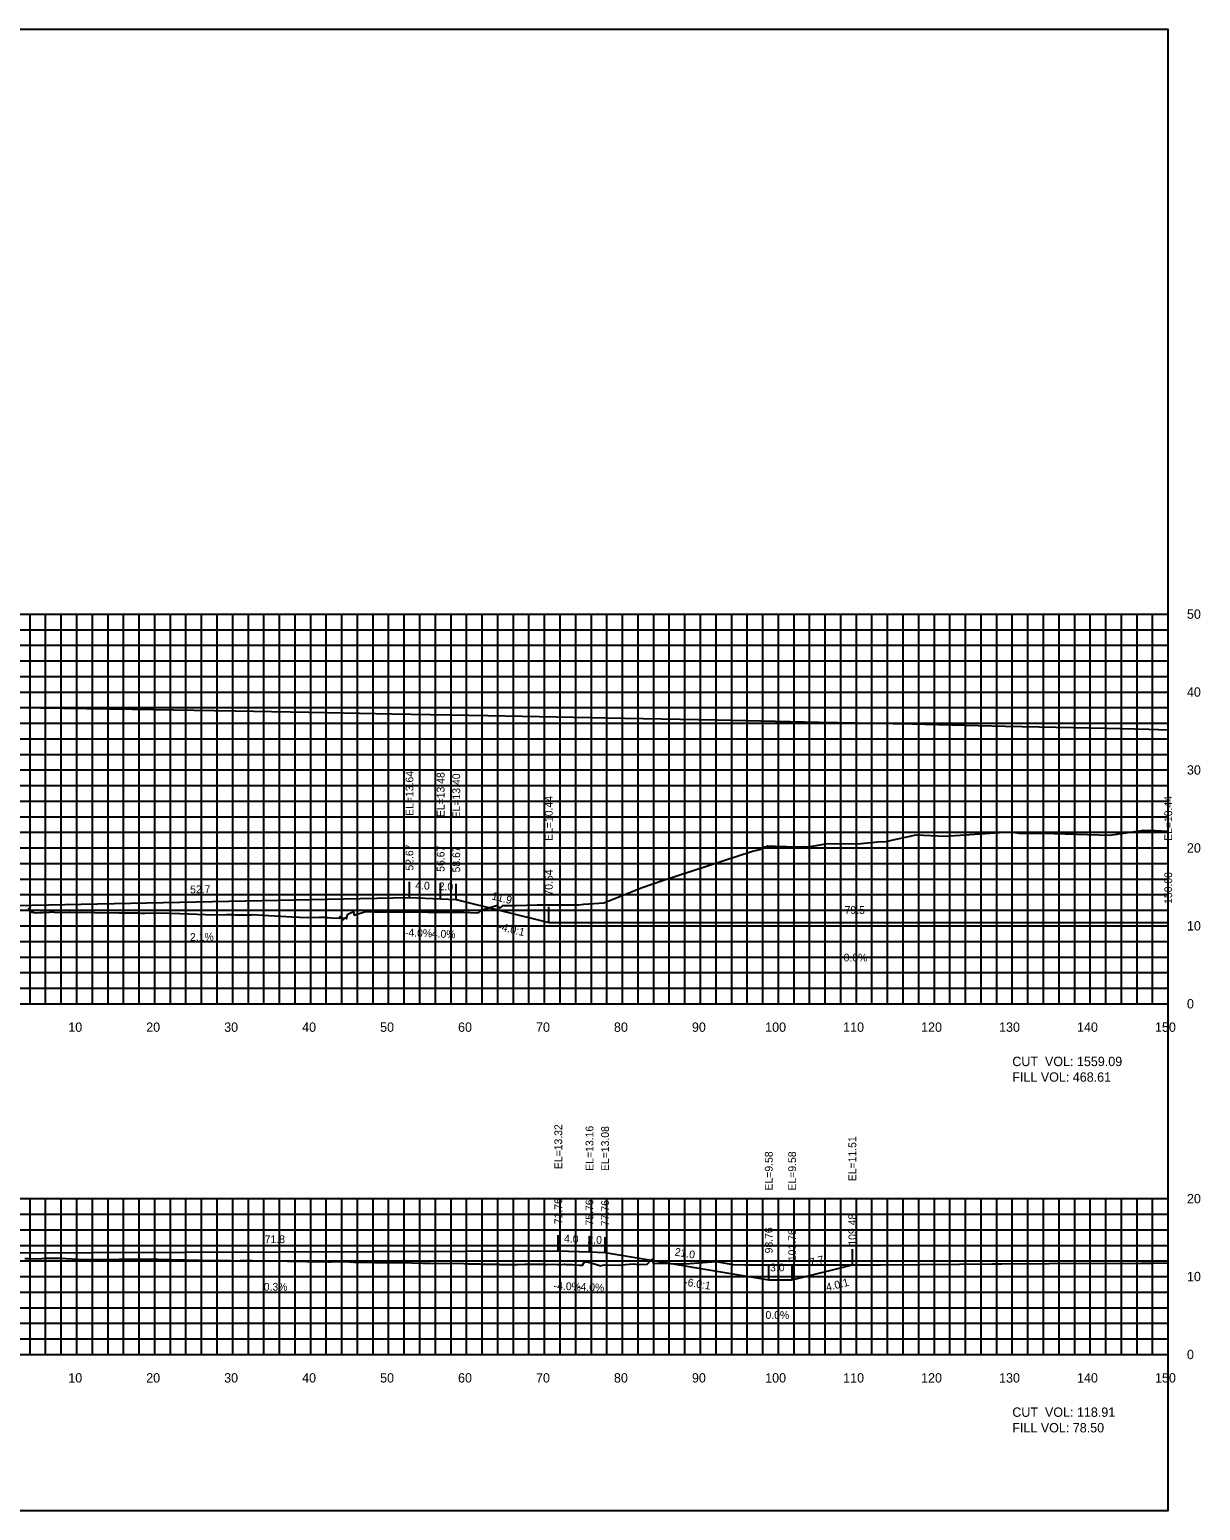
# Model space of a CAD drawing. Extents: x 1797419 to 1809236, y 248759 to 251512.
# Drawn here: x 1802974.9 to 1803125.1, y 250417.3 to 250607.3 of the extents above; entities that cross this region are included whole.
import ezdxf

# ---------------------------------------------------------------- set-up
doc = ezdxf.new("R2010")
doc.units = 0
for name, color, linetype in [('10', 7, 'Continuous'), ('3', 7, 'Continuous'), ('31', 7, 'Continuous'), ('4', 7, 'Continuous'), ('60', 7, 'Continuous'), ('ANNO-TXT', 7, 'Continuous'), ('CL-CNST', 7, 'Continuous'), ('Level 62', 7, 'Continuous'), ('M-ROADS', 7, 'Continuous')]:
    doc.layers.add(name, color=color, linetype=linetype)

msp = doc.modelspace()

# ---------------------------------------------------------------- linework, layer by layer
for p, q in [((1803023.67, 250495.9), (1803023.67, 250497.9)), ((1803027.67, 250495.74), (1803027.67, 250497.74)), ((1803029.67, 250495.66), (1803029.67, 250497.66)), ((1803041.54, 250492.69), (1803041.54, 250494.69)), ((1803121, 250492.69), (1803121, 250494.69)), ((1803042.76, 250450.57), (1803042.76, 250452.57)), ((1803046.76, 250450.41), (1803046.76, 250452.41)), ((1803048.76, 250450.33), (1803048.76, 250452.33)), ((1803080.48, 250448.76), (1803080.48, 250450.76)), ((1803069.76, 250446.83), (1803069.76, 250448.83)), ((1803072.76, 250446.83), (1803072.76, 250448.83))]:
    msp.add_line(p, q)
msp.add_lwpolyline([(1802821, 250417.26), (1803121, 250417.26), (1803121, 250607.26), (1802821, 250607.26)], close=True)
at = {"layer": '60'}
for p, q in [((1803121, 250482.26), (1803121, 250532.26)), ((1803121.06, 250532.26), (1803121, 250532.26)), ((1803121.06, 250522.26), (1803121, 250522.26)), ((1803121.06, 250512.26), (1803121, 250512.26)), ((1803121.06, 250502.26), (1803121, 250502.26)), ((1803121.06, 250492.26), (1803121, 250492.26)), ((1802821, 250482.26), (1803121, 250482.26)), ((1802981, 250482.2), (1802981, 250482.26)), ((1802991, 250482.2), (1802991, 250482.26)), ((1803001, 250482.2), (1803001, 250482.26)), ((1803011, 250482.2), (1803011, 250482.26)), ((1803021, 250482.2), (1803021, 250482.26)), ((1803031, 250482.2), (1803031, 250482.26)), ((1803041, 250482.2), (1803041, 250482.26)), ((1803051, 250482.2), (1803051, 250482.26)), ((1803061, 250482.2), (1803061, 250482.26)), ((1803071, 250482.2), (1803071, 250482.26)), ((1803081, 250482.2), (1803081, 250482.26)), ((1803091, 250482.2), (1803091, 250482.26)), ((1803101, 250482.2), (1803101, 250482.26)), ((1803111, 250482.2), (1803111, 250482.26)), ((1803121, 250482.2), (1803121, 250482.26)), ((1803121.06, 250482.26), (1803121, 250482.26)), ((1803121, 250437.26), (1803121, 250457.26)), ((1803121.06, 250457.26), (1803121, 250457.26)), ((1803121.06, 250447.26), (1803121, 250447.26)), ((1802821, 250437.26), (1803121, 250437.26)), ((1802981, 250437.2), (1802981, 250437.26)), ((1802991, 250437.2), (1802991, 250437.26)), ((1803001, 250437.2), (1803001, 250437.26)), ((1803011, 250437.2), (1803011, 250437.26)), ((1803021, 250437.2), (1803021, 250437.26)), ((1803031, 250437.2), (1803031, 250437.26)), ((1803041, 250437.2), (1803041, 250437.26)), ((1803051, 250437.2), (1803051, 250437.26)), ((1803061, 250437.2), (1803061, 250437.26)), ((1803071, 250437.2), (1803071, 250437.26)), ((1803081, 250437.2), (1803081, 250437.26)), ((1803091, 250437.2), (1803091, 250437.26)), ((1803101, 250437.2), (1803101, 250437.26)), ((1803111, 250437.2), (1803111, 250437.26)), ((1803121, 250437.2), (1803121, 250437.26)), ((1803121.06, 250437.26), (1803121, 250437.26))]:
    msp.add_line(p, q, dxfattribs=at)
at = {"layer": 'CL-CNST'}
for points in [[(1802963.13, 250520.45), (1802976.35, 250520.24), (1802988.13, 250520.05), (1803001.31, 250519.83), (1803013.13, 250519.62), (1803021.41, 250519.47), (1803028.86, 250519.34), (1803028.86, 250519.34), (1803028.86, 250519.34), (1803033.73, 250519.25), (1803038.13, 250519.17), (1803051.25, 250518.91), (1803063.13, 250518.68), (1803076.21, 250518.41), (1803088.13, 250518.16), (1803100.07, 250517.9), (1803113.13, 250517.61), (1803118.53, 250517.49), (1803121, 250517.43)], [(1802904, 250493.23), (1802906, 250493.31), (1802910, 250493.47), (1802971, 250494.81), (1803023.67, 250495.9), (1803027.67, 250495.74), (1803029.67, 250495.66), (1803041.54, 250492.69), (1803121, 250492.69)], [(1802862.48, 250449.62), (1802880, 250445.24), (1802883, 250445.24), (1802904, 250448.74), (1802906, 250448.82), (1802910, 250448.98), (1802971, 250450.32), (1803042.76, 250450.57), (1803046.76, 250450.41), (1803048.76, 250450.33), (1803069.76, 250446.83), (1803072.76, 250446.83), (1803080.48, 250448.76)]]:
    msp.add_lwpolyline(points, dxfattribs=at)
at = {"layer": 'Level 62'}
for p, q in [((1802821, 250532.26), (1803121, 250532.26)), ((1802975, 250482.26), (1802975, 250532.26)), ((1802977, 250482.26), (1802977, 250532.26)), ((1802979, 250482.26), (1802979, 250532.26)), ((1802981, 250482.26), (1802981, 250532.26)), ((1802983, 250482.26), (1802983, 250532.26)), ((1802985, 250482.26), (1802985, 250532.26)), ((1802987, 250482.26), (1802987, 250532.26)), ((1802989, 250482.26), (1802989, 250532.26)), ((1802991, 250482.26), (1802991, 250532.26)), ((1802993, 250482.26), (1802993, 250532.26)), ((1802995, 250482.26), (1802995, 250532.26)), ((1802997, 250482.26), (1802997, 250532.26)), ((1802999, 250482.26), (1802999, 250532.26)), ((1803001, 250482.26), (1803001, 250532.26)), ((1803003, 250482.26), (1803003, 250532.26)), ((1803005, 250482.26), (1803005, 250532.26)), ((1803007, 250482.26), (1803007, 250532.26)), ((1803009, 250482.26), (1803009, 250532.26)), ((1803011, 250482.26), (1803011, 250532.26)), ((1803013, 250482.26), (1803013, 250532.26)), ((1803015, 250482.26), (1803015, 250532.26)), ((1803017, 250482.26), (1803017, 250532.26)), ((1803019, 250482.26), (1803019, 250532.26)), ((1803021, 250482.26), (1803021, 250532.26)), ((1803023, 250482.26), (1803023, 250532.26)), ((1803025, 250482.26), (1803025, 250532.26)), ((1803027, 250482.26), (1803027, 250532.26)), ((1803029, 250482.26), (1803029, 250532.26)), ((1803031, 250482.26), (1803031, 250532.26)), ((1803033, 250482.26), (1803033, 250532.26)), ((1803035, 250482.26), (1803035, 250532.26)), ((1803037, 250482.26), (1803037, 250532.26)), ((1803039, 250482.26), (1803039, 250532.26)), ((1803041, 250482.26), (1803041, 250532.26)), ((1803043, 250482.26), (1803043, 250532.26)), ((1803045, 250482.26), (1803045, 250532.26)), ((1803047, 250482.26), (1803047, 250532.26)), ((1803049, 250482.26), (1803049, 250532.26)), ((1803051, 250482.26), (1803051, 250532.26)), ((1803053, 250482.26), (1803053, 250532.26)), ((1803055, 250482.26), (1803055, 250532.26)), ((1803057, 250482.26), (1803057, 250532.26)), ((1803059, 250482.26), (1803059, 250532.26)), ((1803061, 250482.26), (1803061, 250532.26)), ((1803063, 250482.26), (1803063, 250532.26)), ((1803065, 250482.26), (1803065, 250532.26)), ((1803067, 250482.26), (1803067, 250532.26)), ((1803069, 250482.26), (1803069, 250532.26)), ((1803071, 250482.26), (1803071, 250532.26)), ((1803073, 250482.26), (1803073, 250532.26)), ((1803075, 250482.26), (1803075, 250532.26)), ((1803077, 250482.26), (1803077, 250532.26)), ((1803079, 250482.26), (1803079, 250532.26)), ((1803081, 250482.26), (1803081, 250532.26)), ((1803083, 250482.26), (1803083, 250532.26)), ((1803085, 250482.26), (1803085, 250532.26)), ((1803087, 250482.26), (1803087, 250532.26)), ((1803089, 250482.26), (1803089, 250532.26)), ((1803091, 250482.26), (1803091, 250532.26)), ((1803093, 250482.26), (1803093, 250532.26)), ((1803095, 250482.26), (1803095, 250532.26)), ((1803097, 250482.26), (1803097, 250532.26)), ((1803099, 250482.26), (1803099, 250532.26)), ((1803101, 250482.26), (1803101, 250532.26)), ((1803103, 250482.26), (1803103, 250532.26)), ((1803105, 250482.26), (1803105, 250532.26)), ((1803107, 250482.26), (1803107, 250532.26)), ((1803109, 250482.26), (1803109, 250532.26)), ((1803111, 250482.26), (1803111, 250532.26)), ((1803113, 250482.26), (1803113, 250532.26)), ((1803115, 250482.26), (1803115, 250532.26)), ((1803117, 250482.26), (1803117, 250532.26)), ((1803119, 250482.26), (1803119, 250532.26)), ((1803121, 250482.26), (1803121, 250532.26)), ((1802821, 250530.26), (1803121, 250530.26)), ((1802821, 250528.26), (1803121, 250528.26)), ((1802821, 250526.26), (1803121, 250526.26)), ((1802821, 250524.26), (1803121, 250524.26)), ((1802821, 250522.26), (1803121, 250522.26)), ((1802821, 250520.26), (1803121, 250520.26)), ((1802821, 250518.26), (1803121, 250518.26)), ((1802821, 250516.26), (1803121, 250516.26)), ((1802821, 250514.26), (1803121, 250514.26)), ((1802821, 250512.26), (1803121, 250512.26)), ((1802821, 250510.26), (1803121, 250510.26)), ((1802821, 250508.26), (1803121, 250508.26)), ((1802821, 250506.26), (1803121, 250506.26)), ((1802821, 250504.26), (1803121, 250504.26)), ((1802821, 250502.26), (1803121, 250502.26)), ((1802821, 250500.26), (1803121, 250500.26)), ((1802821, 250498.26), (1803121, 250498.26)), ((1802821, 250496.26), (1803121, 250496.26)), ((1802821, 250494.26), (1803121, 250494.26)), ((1802821, 250492.26), (1803121, 250492.26)), ((1802821, 250490.26), (1803121, 250490.26)), ((1802821, 250488.26), (1803121, 250488.26)), ((1802821, 250486.26), (1803121, 250486.26)), ((1802821, 250484.26), (1803121, 250484.26)), ((1802821, 250482.26), (1803121, 250482.26)), ((1802821, 250457.26), (1803121, 250457.26)), ((1802975, 250437.26), (1802975, 250457.26)), ((1802977, 250437.26), (1802977, 250457.26)), ((1802979, 250437.26), (1802979, 250457.26)), ((1802981, 250437.26), (1802981, 250457.26)), ((1802983, 250437.26), (1802983, 250457.26)), ((1802985, 250437.26), (1802985, 250457.26)), ((1802987, 250437.26), (1802987, 250457.26)), ((1802989, 250437.26), (1802989, 250457.26)), ((1802991, 250437.26), (1802991, 250457.26)), ((1802993, 250437.26), (1802993, 250457.26)), ((1802995, 250437.26), (1802995, 250457.26)), ((1802997, 250437.26), (1802997, 250457.26)), ((1802999, 250437.26), (1802999, 250457.26)), ((1803001, 250437.26), (1803001, 250457.26)), ((1803003, 250437.26), (1803003, 250457.26)), ((1803005, 250437.26), (1803005, 250457.26)), ((1803007, 250437.26), (1803007, 250457.26)), ((1803009, 250437.26), (1803009, 250457.26)), ((1803011, 250437.26), (1803011, 250457.26)), ((1803013, 250437.26), (1803013, 250457.26)), ((1803015, 250437.26), (1803015, 250457.26)), ((1803017, 250437.26), (1803017, 250457.26)), ((1803019, 250437.26), (1803019, 250457.26)), ((1803021, 250437.26), (1803021, 250457.26)), ((1803023, 250437.26), (1803023, 250457.26)), ((1803025, 250437.26), (1803025, 250457.26)), ((1803027, 250437.26), (1803027, 250457.26)), ((1803029, 250437.26), (1803029, 250457.26)), ((1803031, 250437.26), (1803031, 250457.26)), ((1803033, 250437.26), (1803033, 250457.26)), ((1803035, 250437.26), (1803035, 250457.26)), ((1803037, 250437.26), (1803037, 250457.26)), ((1803039, 250437.26), (1803039, 250457.26)), ((1803041, 250437.26), (1803041, 250457.26)), ((1803043, 250437.26), (1803043, 250457.26)), ((1803045, 250437.26), (1803045, 250457.26)), ((1803047, 250437.26), (1803047, 250457.26)), ((1803049, 250437.26), (1803049, 250457.26)), ((1803051, 250437.26), (1803051, 250457.26)), ((1803053, 250437.26), (1803053, 250457.26)), ((1803055, 250437.26), (1803055, 250457.26)), ((1803057, 250437.26), (1803057, 250457.26)), ((1803059, 250437.26), (1803059, 250457.26)), ((1803061, 250437.26), (1803061, 250457.26)), ((1803063, 250437.26), (1803063, 250457.26)), ((1803065, 250437.26), (1803065, 250457.26)), ((1803067, 250437.26), (1803067, 250457.26)), ((1803069, 250437.26), (1803069, 250457.26)), ((1803071, 250437.26), (1803071, 250457.26)), ((1803073, 250437.26), (1803073, 250457.26)), ((1803075, 250437.26), (1803075, 250457.26)), ((1803077, 250437.26), (1803077, 250457.26)), ((1803079, 250437.26), (1803079, 250457.26)), ((1803081, 250437.26), (1803081, 250457.26)), ((1803083, 250437.26), (1803083, 250457.26)), ((1803085, 250437.26), (1803085, 250457.26)), ((1803087, 250437.26), (1803087, 250457.26)), ((1803089, 250437.26), (1803089, 250457.26)), ((1803091, 250437.26), (1803091, 250457.26)), ((1803093, 250437.26), (1803093, 250457.26)), ((1803095, 250437.26), (1803095, 250457.26)), ((1803097, 250437.26), (1803097, 250457.26)), ((1803099, 250437.26), (1803099, 250457.26)), ((1803101, 250437.26), (1803101, 250457.26)), ((1803103, 250437.26), (1803103, 250457.26)), ((1803105, 250437.26), (1803105, 250457.26)), ((1803107, 250437.26), (1803107, 250457.26)), ((1803109, 250437.26), (1803109, 250457.26)), ((1803111, 250437.26), (1803111, 250457.26)), ((1803113, 250437.26), (1803113, 250457.26)), ((1803115, 250437.26), (1803115, 250457.26)), ((1803117, 250437.26), (1803117, 250457.26)), ((1803119, 250437.26), (1803119, 250457.26)), ((1803121, 250437.26), (1803121, 250457.26)), ((1802821, 250455.26), (1803121, 250455.26)), ((1802821, 250453.26), (1803121, 250453.26)), ((1802821, 250451.26), (1803121, 250451.26)), ((1802821, 250449.26), (1803121, 250449.26)), ((1802821, 250447.26), (1803121, 250447.26)), ((1802821, 250445.26), (1803121, 250445.26)), ((1802821, 250443.26), (1803121, 250443.26)), ((1802821, 250441.26), (1803121, 250441.26)), ((1802821, 250439.26), (1803121, 250439.26)), ((1802821, 250437.26), (1803121, 250437.26))]:
    msp.add_line(p, q, dxfattribs=at)
at = {"layer": 'M-ROADS'}
for points in [[(1802974.82, 250494.57), (1802975.06, 250494.21), (1802975.16, 250494.05), (1802975.17, 250494.03), (1802975.18, 250494.03), (1802975.27, 250494.04), (1802975.32, 250494.02), (1802975.35, 250494.02), (1802975.38, 250494.02), (1802975.39, 250494.01), (1802975.4, 250494.01), (1802975.41, 250494.01), (1802975.41, 250494.01), (1802975.42, 250494.01), (1802975.43, 250493.97), (1802975.72, 250493.94), (1802976.27, 250493.97), (1802976.7, 250493.98), (1802977.49, 250494.03), (1802978.01, 250494.04), (1802978.05, 250494.03), (1802978.57, 250493.95), (1802980.11, 250494.03), (1802986.44, 250493.93), (1802986.49, 250493.93), (1802986.5, 250493.93), (1802988.87, 250493.94), (1802989.19, 250493.89), (1802989.74, 250493.89), (1802991.44, 250493.93), (1802994.2, 250493.84), (1802998.63, 250493.69), (1803000.18, 250493.72), (1803000.74, 250493.73), (1803000.82, 250493.73), (1803000.96, 250493.71), (1803001.3, 250493.67), (1803001.47, 250493.66), (1803002.76, 250493.68), (1803003.36, 250493.66), (1803003.57, 250493.7), (1803004.8, 250493.62), (1803007.16, 250493.49), (1803008.59, 250493.42), (1803010.56, 250493.33), (1803012.07, 250493.37), (1803012.75, 250493.37), (1803012.9, 250493.35), (1803013.23, 250493.31), (1803013.65, 250493.27), (1803014.69, 250493.26), (1803014.77, 250493.45), (1803014.88, 250493.26), (1803014.91, 250493.26), (1803015.16, 250493.13), (1803015.17, 250493.05), (1803015.18, 250493.25), (1803015.18, 250493.14), (1803015.24, 250493.22), (1803015.24, 250493.21), (1803015.34, 250493.26), (1803015.4, 250493.29), (1803015.51, 250493.35), (1803015.54, 250493.3), (1803015.59, 250493.14), (1803015.61, 250493.25), (1803015.76, 250493.75), (1803016.47, 250494.08), (1803016.49, 250494.06), (1803016.57, 250493.63), (1803018.01, 250494.08), (1803019.2, 250494.05), (1803021.99, 250494.05), (1803026.01, 250494.01), (1803027.83, 250494.01), (1803030.24, 250494.01), (1803030.35, 250494.01), (1803030.48, 250494.01), (1803030.6, 250494), (1803032.33, 250493.94), (1803032.55, 250493.98), (1803032.98, 250494.3), (1803034.85, 250494.89), (1803035.24, 250494.52), (1803035.7, 250494.87), (1803037.25, 250494.89), (1803040.03, 250494.94), (1803043.98, 250494.95), (1803045.31, 250494.94), (1803045.4, 250494.94), (1803046.02, 250495.03), (1803048.59, 250495.22), (1803053.5, 250497.19), (1803056.25, 250498.12), (1803067.66, 250501.82), (1803068.61, 250502.05), (1803069.27, 250502.4), (1803069.43, 250502.41), (1803069.66, 250502.53), (1803071.57, 250502.45), (1803072.04, 250502.43), (1803073.22, 250502.38), (1803074.27, 250502.42), (1803074.34, 250502.38), (1803074.87, 250502.4), (1803077.06, 250502.78), (1803081.61, 250502.84), (1803084.19, 250503.06), (1803084.47, 250503.02), (1803085.02, 250503.14), (1803085.31, 250503.2), (1803088.66, 250503.92), (1803092.4, 250503.77), (1803100.66, 250504.34), (1803101.89, 250504.15), (1803103.86, 250504.15), (1803105.81, 250504.15), (1803106.31, 250504.15), (1803106.38, 250504.12), (1803113.53, 250503.89), (1803117.6, 250504.49), (1803117.77, 250504.52), (1803118.17, 250504.51), (1803118.45, 250504.52), (1803121, 250504.41)], [(1802974.33, 250449.58), (1802975.07, 250449.59), (1802975.66, 250449.54), (1802976.57, 250449.59), (1802976.84, 250449.61), (1802977.17, 250449.62), (1802978.08, 250449.62), (1802978.88, 250449.6), (1802981.91, 250449.45), (1802983.1, 250449.46), (1802986.44, 250449.47), (1802987.57, 250449.49), (1802988.83, 250449.48), (1802988.95, 250449.47), (1802989.77, 250449.48), (1802990.85, 250449.47), (1802991.39, 250449.48), (1802992.96, 250449.44), (1802998.57, 250449.31), (1803000.66, 250449.33), (1803000.69, 250449.33), (1803001.15, 250449.29), (1803001.95, 250449.31), (1803002.2, 250449.31), (1803003.14, 250449.31), (1803003.51, 250449.31), (1803003.55, 250449.31), (1803005.52, 250449.27), (1803010.49, 250449.17), (1803011.07, 250449.17), (1803012.81, 250449.17), (1803013.22, 250449.15), (1803013.29, 250449.15), (1803013.59, 250449.15), (1803015.44, 250449.17), (1803016.54, 250449.12), (1803017.71, 250449.11), (1803019.17, 250449.08), (1803019.22, 250449.06), (1803019.23, 250449.05), (1803019.84, 250449.05), (1803020.83, 250449.05), (1803021.19, 250449.05), (1803021.41, 250449.05), (1803022.55, 250449.06), (1803023.59, 250449.06), (1803023.65, 250449.05), (1803023.98, 250449.04), (1803023.99, 250449.03), (1803024.02, 250449.03), (1803025.37, 250448.97), (1803025.88, 250448.97), (1803026.17, 250448.97), (1803026.35, 250448.97), (1803030.63, 250448.92), (1803031.25, 250448.9), (1803032.72, 250448.87), (1803033.12, 250448.86), (1803033.43, 250448.86), (1803035.14, 250448.83), (1803035.24, 250448.82), (1803035.33, 250448.82), (1803036.12, 250448.81), (1803037.12, 250448.82), (1803037.57, 250448.82), (1803038.48, 250448.83), (1803039.23, 250448.83), (1803039.62, 250448.83), (1803040, 250448.83), (1803040.88, 250448.83), (1803041.07, 250448.8), (1803041.17, 250448.8), (1803041.26, 250448.8), (1803042.06, 250448.84), (1803042.66, 250448.8), (1803042.78, 250448.79), (1803042.86, 250448.78), (1803043.53, 250448.83), (1803043.57, 250448.83), (1803043.79, 250448.79), (1803044.57, 250448.81), (1803045, 250448.76), (1803045.51, 250448.71), (1803045.85, 250448.74), (1803046.12, 250449.13), (1803046.16, 250449.1), (1803046.51, 250449.15), (1803048.1, 250448.67), (1803048.15, 250448.65), (1803048.64, 250448.77), (1803050.45, 250448.71), (1803051.05, 250448.78), (1803051.36, 250448.8), (1803052.35, 250448.87), (1803053.13, 250448.79), (1803054.18, 250448.84), (1803054.82, 250449.49), (1803054.93, 250448.96), (1803059.05, 250448.89), (1803063.02, 250449.19), (1803065.17, 250448.8), (1803066.67, 250448.75), (1803077.77, 250448.77), (1803082.06, 250448.76), (1803084.09, 250448.78), (1803094.21, 250448.84), (1803098.43, 250448.9), (1803099.66, 250448.91), (1803105.72, 250448.92), (1803117.53, 250448.98), (1803117.84, 250448.98), (1803119.04, 250448.99), (1803120.86, 250449.03), (1803121, 250449.03)]]:
    msp.add_lwpolyline(points, dxfattribs=at)

# ---------------------------------------------------------------- texts
for s, rotation, p in [('-4.0:1', 345.9638, (1803035, 250491.75)), ('-6.0:1', 350.5377, (1803058.85, 250446.12)), ('4.0:1', 14.0362, (1803077.23, 250445.37))]:
    msp.add_text(s, height=1, rotation=rotation).set_placement(p)
at = {"layer": '10'}
for s, p in [('10', (1802979.9, 250478.66)), ('20', (1802989.9, 250478.66)), ('30', (1802999.9, 250478.66)), ('40', (1803009.9, 250478.66)), ('50', (1803019.9, 250478.66)), ('60', (1803029.9, 250478.66)), ('70', (1803039.9, 250478.66)), ('80', (1803049.9, 250478.66)), ('90', (1803059.9, 250478.66)), ('100', (1803069.3, 250478.66)), ('110', (1803079.3, 250478.66)), ('120', (1803089.3, 250478.66)), ('130', (1803099.3, 250478.66)), ('140', (1803109.3, 250478.66)), ('150', (1803119.3, 250478.66)), ('10', (1802979.9, 250433.66)), ('20', (1802989.9, 250433.66)), ('30', (1802999.9, 250433.66)), ('40', (1803009.9, 250433.66)), ('50', (1803019.9, 250433.66)), ('60', (1803029.9, 250433.66)), ('70', (1803039.9, 250433.66)), ('80', (1803049.9, 250433.66)), ('90', (1803059.9, 250433.66)), ('100', (1803069.3, 250433.66)), ('110', (1803079.3, 250433.66)), ('120', (1803089.3, 250433.66)), ('130', (1803099.3, 250433.66)), ('140', (1803109.3, 250433.66)), ('150', (1803119.3, 250433.66))]:
    msp.add_text(s, height=1.2, dxfattribs=at).set_placement(p)
at = {"layer": '3'}
for s, p in [('EL=13.64', (1803024.17, 250506.37)), ('EL=13.48', (1803028.17, 250506.21)), ('EL=13.40', (1803030.17, 250506.05)), ('EL=10.44', (1803042.04, 250503.16)), ('EL=10.44', (1803121.5, 250503.16)), ('52.67', (1803024.17, 250499.35)), ('56.67', (1803028.17, 250499.19)), ('58.67', (1803030.17, 250499.11)), ('70.54', (1803042.04, 250496.14)), ('150.00', (1803121.5, 250495.07)), ('EL=13.32', (1803043.26, 250461.04)), ('EL=13.16', (1803047.26, 250460.84)), ('EL=13.08', (1803049.26, 250460.8)), ('EL=11.51', (1803080.98, 250459.49)), ('EL=9.58', (1803070.26, 250458.3)), ('EL=9.58', (1803073.26, 250458.3)), ('71.76', (1803043.26, 250453.97)), ('75.76', (1803047.26, 250453.81)), ('77.76', (1803049.26, 250453.73)), ('109.48', (1803080.98, 250451.22)), ('98.76', (1803070.26, 250450.23)), ('101.76', (1803073.26, 250449.24))]:
    msp.add_text(s, height=1, rotation=90, dxfattribs=at).set_placement(p)
at = {"layer": '31'}
for s, p in [('50', (1803123.4, 250531.66)), ('40', (1803123.4, 250521.66)), ('30', (1803123.4, 250511.66)), ('20', (1803123.4, 250501.66)), ('10', (1803123.4, 250491.66)), ('0', (1803123.4, 250481.66)), ('20', (1803123.4, 250456.66)), ('10', (1803123.4, 250446.66)), ('0', (1803123.4, 250436.66))]:
    msp.add_text(s, height=1.2, dxfattribs=at).set_placement(p)
at = {"layer": '4'}
for s, rotation, p in [('4.0', 357.7094, (1803024.4, 250496.97)), ('52.7', 1.1877, (1802995.54, 250496.42)), ('2.0', 357.7094, (1803027.4, 250496.85)), ('11.9', 345.9638, (1803034.15, 250495.67)), ('2.1%', 1.1877, (1802995.53, 250490.31)), ('-4.0%', 357.7094, (1803023.07, 250490.92)), ('-4.0%', 357.7094, (1803026.07, 250490.8)), ('71.8', 0.2, (1803005.1, 250451.54)), ('4.0', 357.7094, (1803043.48, 250451.64)), ('2.0', 357.7094, (1803046.48, 250451.52)), ('21.0', 350.5377, (1803057.64, 250449.97)), ('7.7', 14.0362, (1803075.11, 250448.55)), ('0.3%', 0.2, (1803004.98, 250445.44)), ('-4.0%', 357.7094, (1803042.15, 250445.59)), ('-4.0%', 357.7094, (1803045.15, 250445.47))]:
    msp.add_text(s, height=1, rotation=rotation, dxfattribs=at).set_placement(p)
for s, p in [('79.5', (1803079.49, 250493.79)), ('0.0%', (1803079.36, 250487.69)), ('3.0', (1803069.93, 250447.93)), ('0.0%', (1803069.34, 250441.83))]:
    msp.add_text(s, height=1, dxfattribs=at).set_placement(p)
at = {"layer": 'ANNO-TXT'}
for s, p in [('CUT  VOL: 1559.09', (1803101, 250474.26)), ('FILL VOL: 468.61', (1803101, 250472.26)), ('CUT  VOL: 118.91', (1803101, 250429.26)), ('FILL VOL: 78.50', (1803101, 250427.26))]:
    msp.add_text(s, height=1.2, dxfattribs=at).set_placement(p)

doc.saveas('drawing.dxf')
